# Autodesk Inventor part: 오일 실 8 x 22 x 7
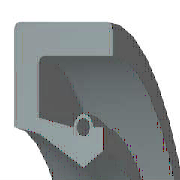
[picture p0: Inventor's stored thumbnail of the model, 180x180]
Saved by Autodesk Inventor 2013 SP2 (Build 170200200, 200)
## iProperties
IsCustomPart: 1
Created: 2012-02
Part Number: 오일 실 8 x 22 x 7
Material: 고무
Description: 오일-실
Document SubType Name: Modeling
Standard: KS B 2804
Designer: test
Standards Organization: KS
Language: ko-KR
Size Designation: S - 8 22 7
Categories: <MemberInstance><Categories><Category DisplayName="샤프트 부품" InternalName="7f7aeb1f-a693-4053-b835-cee3144e0d98" Mnemonic="SHFT"><Category DisplayName="실링" Intern
Density: 0.93 g/cm^3
Author: test
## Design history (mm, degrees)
revolve "본체" stored, may be unused: angle "d17" = 90 deg
revolve "스프링1" stored, may be unused: angle "d18" = 90 deg
body "Solid1"
sketch "스케치1"
  geometry: L1 (0, 11)-(7, 11); L2 (7, 11)-(7, 9.75); L3 (7, 9.75)-(1.75, 9.75); L4 (0, 11)-(0, 6.1); L5 (0, 6.1)-(1.75, 5.75); L6 (1.75, 5.75)-(4.9, 4); L7 (4.9, 4)-(0, 4); L8 (6.3, 4.875)-(6.3, 6.1); L9 (0, 0)-(9.586, 0) reference; L10 (4.9, 4)-(6.3, 4.875); L11 (0, 18)-(0, -3) reference; L12 (-1.917, 0)-(11.503, 0) reference; L13 (4.2, 6.1)-(1.75, 6.59); L14 (1.75, 6.59)-(1.75, 9.75); L15 (6.3, 6.1)-(5.6, 6.1); C1 r 0.455 at (4.9, 6.1); A1 r 0.7 centre (4.9, 6.1) between (5.6, 6.1) and (4.2, 6.1)
  constraints: 26 end point, 5 horizontal alignment, 4 perpendicular, 2 centre point, 2 collinear, 2 horizontal, 2 parallel, 2 point on circle, 2 point on line, 2 vertical alignment, 1 coincident
  dimensions: "d0" = 22 diameter of L1 L9 (= SD2); "d1" = 9.75 diameter of L8.start L9 (= ABDM); "d2" = 1.25 distance of L1.end L2.end (computed from SD); "d3" = 0.91 diameter of C1 (= SPDI); "d4" = 1.4 diameter of A1 (= SPDA); "d5" = 8 diameter of L6.end L9 (= NND); "d6" = 11.5 diameter of L5.end L9 (= TKDM); "d7" = 12.2 diameter of L4.end L9 (= HLDM); "d8" = 4.9 distance from line of C1.centre L4 (= SPDST); "d9" = 6.3 distance between parallel lines of L8 L4 (= SDI); "d10" = 7 distance between parallel lines of L2 L4 (= SWDT); "d12" = 1.75 distance between parallel lines of L14 L4 (= SD)
fillet "모깎기1" dims "d11" = 0.3 (= RR)
other parameters: "SD2" = 22 [user parameter; used in 1 equation term], "SWDT" = 7 [user parameter; used in 1 equation term], "RR" = 0.3 [user parameter; used in 1 equation term], "SD" = 1.75 [user parameter; used in 2 equation terms], "NND" = 8 [user parameter; used in 1 equation term], "SPDA" = 1.4 [user parameter; used in 1 equation term], "SPDI" = 0.91 [user parameter; used in 1 equation term], "TKDM" = 11.5 [user parameter; used in 1 equation term], "HLDM" = 12.2 [user parameter; used in 1 equation term], "ABDM" = 9.75 [user parameter; used in 1 equation term], "SDI" = 6.3 [user parameter; used in 1 equation term], "SPDST" = 4.9 [user parameter; used in 1 equation term], "d13" = 0, "d14" = 0, "d15" = 0, "LAB" = 0.35 [user parameter]
